Omron CX-Programmer project NuevoProyecto (CX-Programmer 9.50)

# PLC NewPLC1: CP1L-E EM

## Program P1_3 (cyclic task 0)
Local symbols
B 100.00 BOOL
Etapa_0 10.00 BOOL
Etapa_1 10.01 BOOL
Etapa_2 10.02 BOOL
Etapa_3 10.03 BOOL
p 0.00 BOOL

### Section Sección1_Programa_principal
; Programa principal (Etapas 0 ... 3)

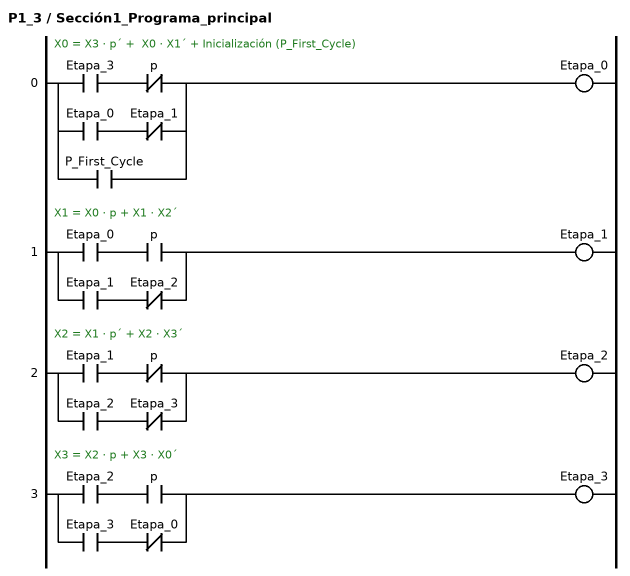
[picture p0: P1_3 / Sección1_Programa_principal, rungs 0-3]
; rung 0: X0 = X3 · p´ +  X0 · X1´ + Inicialización (P_First_Cycle)
LD Etapa_3
ANDNOT p
LD Etapa_0
ANDNOT Etapa_1
ORLD
OR P_First_Cycle
OUT Etapa_0
; rung 1: X1 = X0 · p + X1 · X2´
LD Etapa_0
AND p
LD Etapa_1
ANDNOT Etapa_2
ORLD
OUT Etapa_1
; rung 2: X2 = X1 · p´ + X2 · X3´
LD Etapa_1
ANDNOT p
LD Etapa_2
ANDNOT Etapa_3
ORLD
OUT Etapa_2
; rung 3: X3 = X2 · p + X3 · X0´
LD Etapa_2
AND p
LD Etapa_3
ANDNOT Etapa_0
ORLD
OUT Etapa_3

### Section Sección2_Salida

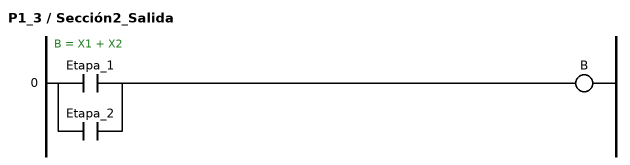
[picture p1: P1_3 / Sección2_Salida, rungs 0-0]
; rung 0: B = X1 + X2
LD Etapa_1
OR Etapa_2
OUT B

### Section Sección3_END
; rung 0
END(001)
